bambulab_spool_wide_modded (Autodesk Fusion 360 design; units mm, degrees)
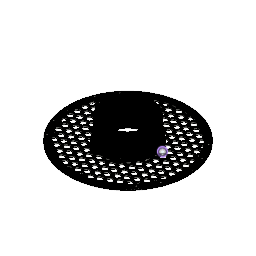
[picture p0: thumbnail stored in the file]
parameter "lattice_diameter" = 10.25
parameter "lattice_thickness" = 3.75
base_mesh_feature "Base Mesh Feature"
convert_mesh "Convert Mesh" bodies "bambulab_spool_wide"
sketch "Sketch13" plane through (0, 0, -16.75) normal (0, 0, 1) x axis (-1, 0, 0)
  line L1 (92.6217, -5.7502) -> (99.4206, -5.9753)
  line L2 (92.483, -7.6633) -> (92.6217, -5.7502)
  line L3 (99.4206, -5.9753) -> (92.483, -7.6633)
  circle C1 centre (15.0006, -94.8189) radius 1.75
  circle C2 centre (-15.0006, -94.8162) radius 1.75
  circle C3 centre (89.6159, -34.4185) radius 1.75
  circle C4 centre (74.6153, 60.4003) radius 1.75
  circle C5 centre (-15.0006, 94.8189) radius 1.75
  circle C6 centre (-89.6159, 34.4185) radius 1.75
  circle C7 centre (-74.6153, -60.4003) radius 1.75
  circle C8 centre (74.6129, -60.399) radius 1.75
  circle C9 centre (89.6135, 34.4171) radius 1.75
  circle C10 centre (15.0006, 94.8162) radius 1.75
  circle C11 centre (-74.6129, 60.399) radius 1.75
  circle C12 centre (-89.6135, -34.4171) radius 1.75
  point P1 (0, 0)
  point P7 (0, 0)
  coincident P1 P7
  dimension "d48" diameter C1 = 3.5
  dimension "d49" diameter C2 = 3.5
  dimension "d51" C-Pattern1-Angle = 360
  dimension "d53" C-Pattern2-Angle = 360
extrude "Extrude5" cut sketch "Sketch13" profile of C3 C4 C6 C7 C8 C9 C11 C12 against normal blind 25
sketch "Sketch14" plane through (0, 0, -17.85) normal (0, 0, 1) x axis (-1, 0, 0)
  line L1 (-23.297, 37.7968) -> (-24.4167, 37.0834)
  line L2 (-2.5625, 4.4384) -> (2.5625, 4.4384)
  line L3 (-5.125, 0) -> (-2.5625, 4.4384)
  line L4 (-2.5625, -4.4384) -> (-5.125, 0)
  line L5 (2.5625, -4.4384) -> (-2.5625, -4.4384)
  line L6 (5.125, 0) -> (2.5625, -4.4384)
  line L7 (2.5625, 4.4384) -> (5.125, 0)
  line L8 (5.125, -12.6268) -> (2.5625, -17.0651)
  line L9 (2.5625, -8.1884) -> (5.125, -12.6268)
  line L10 (-2.5625, -8.1884) -> (2.5625, -8.1884)
  line L11 (-5.125, -12.6268) -> (-2.5625, -8.1884)
  line L12 (-2.5625, -17.0651) -> (-5.125, -12.6268)
  line L13 (2.5625, -17.0651) -> (-2.5625, -17.0651)
  line L14 (0, -45.5) -> (0, 45.5)
  line L15 (-37, 0) -> (37, 0)
  line L16 (16.0601, -6.3134) -> (13.4976, -10.7518)
  line L17 (13.4976, -1.875) -> (16.0601, -6.3134)
  line L18 (8.3726, -1.875) -> (13.4976, -1.875)
  line L19 (5.8101, -6.3134) -> (8.3726, -1.875)
  line L20 (8.3726, -10.7518) -> (5.8101, -6.3134)
  line L21 (13.4976, -10.7518) -> (8.3726, -10.7518)
  line L22 (13.4976, 10.7518) -> (16.0601, 6.3134)
  line L23 (8.3726, 10.7518) -> (13.4976, 10.7518)
  line L24 (5.8101, 6.3134) -> (8.3726, 10.7518)
  line L25 (8.3726, 1.875) -> (5.8101, 6.3134)
  line L26 (13.4976, 1.875) -> (8.3726, 1.875)
  line L27 (16.0601, 6.3134) -> (13.4976, 1.875)
  line L28 (-5.125, -17.0651) -> (-5.125, 10.7518)
  line L29 (16.0601, -17.0651) -> (16.0601, 10.7518)
  line L30 (-5.125, 10.7518) -> (16.0601, 10.7518)
  line L31 (-5.125, -17.0651) -> (16.0601, -17.0651)
  line L32 (-92.4279, -85.5158) -> (-89.8654, -89.9542)
  line L33 (-89.8654, -89.9542) -> (-92.4279, -94.3926)
  line L34 (-92.4279, -94.3926) -> (-97.5529, -94.3926)
  line L35 (-97.5529, -94.3926) -> (-100.1154, -89.9542)
  line L36 (-100.1154, -89.9542) -> (-97.5529, -85.5158)
  line L37 (-97.5529, -85.5158) -> (-92.4279, -85.5158)
  line L38 (-92.4279, -98.1426) -> (-89.8654, -102.581)
  line L39 (-97.5529, -98.1426) -> (-92.4279, -98.1426)
  line L40 (-100.1154, -102.581) -> (-97.5529, -98.1426)
  line L41 (-97.5529, -107.0194) -> (-100.1154, -102.581)
  line L42 (-92.4279, -107.0194) -> (-97.5529, -107.0194)
  line L43 (-89.8654, -102.581) -> (-92.4279, -107.0194)
  line L44 (-100.8005, -96.2676) -> (-103.363, -100.706)
  line L45 (-103.363, -91.8292) -> (-100.8005, -96.2676)
  line L46 (-108.488, -91.8292) -> (-103.363, -91.8292)
  line L47 (-111.0505, -96.2676) -> (-108.488, -91.8292)
  line L48 (-108.488, -100.706) -> (-111.0505, -96.2676)
  line L49 (-103.363, -100.706) -> (-108.488, -100.706)
  line L50 (-108.488, -104.456) -> (-103.363, -104.456)
  line L51 (-103.363, -104.456) -> (-100.8005, -108.8944)
  line L52 (-100.8005, -108.8944) -> (-103.363, -113.3327)
  line L53 (-103.363, -113.3327) -> (-108.488, -113.3327)
  line L54 (-108.488, -113.3327) -> (-111.0505, -108.8944)
  line L55 (-111.0505, -108.8944) -> (-108.488, -104.456)
  line L56 (-71.2428, -85.5158) -> (-68.6803, -89.9542)
  line L57 (-68.6803, -89.9542) -> (-71.2428, -94.3926)
  line L58 (-71.2428, -94.3926) -> (-76.3678, -94.3926)
  line L59 (-76.3678, -94.3926) -> (-78.9303, -89.9542)
  line L60 (-78.9303, -89.9542) -> (-76.3678, -85.5158)
  line L61 (-76.3678, -85.5158) -> (-71.2428, -85.5158)
  line L62 (-71.2428, -98.1426) -> (-68.6803, -102.581)
  line L63 (-76.3678, -98.1426) -> (-71.2428, -98.1426)
  line L64 (-78.9303, -102.581) -> (-76.3678, -98.1426)
  line L65 (-76.3678, -107.0194) -> (-78.9303, -102.581)
  line L66 (-71.2428, -107.0194) -> (-76.3678, -107.0194)
  line L67 (-68.6803, -102.581) -> (-71.2428, -107.0194)
  line L68 (-79.6154, -96.2676) -> (-82.1779, -100.706)
  line L69 (-82.1779, -91.8292) -> (-79.6154, -96.2676)
  line L70 (-87.3029, -91.8292) -> (-82.1779, -91.8292)
  line L71 (-89.8654, -96.2676) -> (-87.3029, -91.8292)
  line L72 (-87.3029, -100.706) -> (-89.8654, -96.2676)
  line L73 (-82.1779, -100.706) -> (-87.3029, -100.706)
  line L74 (-87.3029, -104.456) -> (-82.1779, -104.456)
  line L75 (-82.1779, -104.456) -> (-79.6154, -108.8944)
  line L76 (-79.6154, -108.8944) -> (-82.1779, -113.3327)
  line L77 (-82.1779, -113.3327) -> (-87.3029, -113.3327)
  line L78 (-87.3029, -113.3327) -> (-89.8654, -108.8944)
  line L79 (-89.8654, -108.8944) -> (-87.3029, -104.456)
  line L80 (-50.0577, -85.5158) -> (-47.4952, -89.9542)
  line L81 (-47.4952, -89.9542) -> (-50.0577, -94.3926)
  line L82 (-50.0577, -94.3926) -> (-55.1827, -94.3926)
  line L83 (-55.1827, -94.3926) -> (-57.7452, -89.9542)
  line L84 (-57.7452, -89.9542) -> (-55.1827, -85.5158)
  line L85 (-55.1827, -85.5158) -> (-50.0577, -85.5158)
  line L86 (-50.0577, -98.1426) -> (-47.4952, -102.581)
  line L87 (-55.1827, -98.1426) -> (-50.0577, -98.1426)
  line L88 (-57.7452, -102.581) -> (-55.1827, -98.1426)
  line L89 (-55.1827, -107.0194) -> (-57.7452, -102.581)
  line L90 (-50.0577, -107.0194) -> (-55.1827, -107.0194)
  line L91 (-47.4952, -102.581) -> (-50.0577, -107.0194)
  line L92 (-58.4303, -96.2676) -> (-60.9928, -100.706)
  line L93 (-60.9928, -91.8292) -> (-58.4303, -96.2676)
  line L94 (-66.1178, -91.8292) -> (-60.9928, -91.8292)
  line L95 (-68.6803, -96.2676) -> (-66.1178, -91.8292)
  line L96 (-66.1178, -100.706) -> (-68.6803, -96.2676)
  line L97 (-60.9928, -100.706) -> (-66.1178, -100.706)
  line L98 (-66.1178, -104.456) -> (-60.9928, -104.456)
  line L99 (-60.9928, -104.456) -> (-58.4303, -108.8944)
  line L100 (-58.4303, -108.8944) -> (-60.9928, -113.3327)
  line L101 (-60.9928, -113.3327) -> (-66.1178, -113.3327)
  line L102 (-66.1178, -113.3327) -> (-68.6803, -108.8944)
  line L103 (-68.6803, -108.8944) -> (-66.1178, -104.456)
  line L104 (-28.8726, -85.5158) -> (-26.3101, -89.9542)
  line L105 (-26.3101, -89.9542) -> (-28.8726, -94.3926)
  line L106 (-28.8726, -94.3926) -> (-33.9976, -94.3926)
  line L107 (-33.9976, -94.3926) -> (-36.5601, -89.9542)
  line L108 (-36.5601, -89.9542) -> (-33.9976, -85.5158)
  line L109 (-33.9976, -85.5158) -> (-28.8726, -85.5158)
  line L110 (-28.8726, -98.1426) -> (-26.3101, -102.581)
  line L111 (-33.9976, -98.1426) -> (-28.8726, -98.1426)
  line L112 (-36.5601, -102.581) -> (-33.9976, -98.1426)
  line L113 (-33.9976, -107.0194) -> (-36.5601, -102.581)
  line L114 (-28.8726, -107.0194) -> (-33.9976, -107.0194)
  line L115 (-26.3101, -102.581) -> (-28.8726, -107.0194)
  line L116 (-37.2452, -96.2676) -> (-39.8077, -100.706)
  line L117 (-39.8077, -91.8292) -> (-37.2452, -96.2676)
  line L118 (-44.9327, -91.8292) -> (-39.8077, -91.8292)
  line L119 (-47.4952, -96.2676) -> (-44.9327, -91.8292)
  line L120 (-44.9327, -100.706) -> (-47.4952, -96.2676)
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  point P1 (0, 0)
  point P4 (0, 0)
  point P5 (0, 0)
  point P6 (0, 0)
  point P13 (0, 0)
  point P20 (0, -12.6268)
  point P9 (-5.125, 0)
  point P26 (16.0601, -6.3134)
  point P41 (16.0601, -17.0651)
  point P42 (-5.125, -17.0651)
  point P39 (-5.125, 10.7518)
  point P40 (16.0601, 10.7518)
  point P12 (5.125, 0)
  point P7 (2.5625, 4.4384)
  point P10 (-2.5625, -4.4384)
  point P15 (5.125, -12.6268)
  point P18 (-5.125, -12.6268)
  point P14 (2.5625, -17.0651)
  point P17 (-2.5625, -8.1884)
  point P29 (5.8101, -6.3134)
  point P32 (16.0601, 6.3134)
  point P35 (5.8101, 6.3134)
  coincident P1 P4
  coincident P1 P5
  coincident P1 P6
  coincident P5 P13
  vertical L14
  horizontal L15
  coincident P1 L14
  midpoint P4 L15
  midpoint P1 L14
  coincident P20 L14
  parallel L5 L15
  parallel L15 L21
  parallel L15 L26
  vertical L28
  vertical L29
  coincident P9 L28
  coincident P26 L29
  perpendicular L29 L30
  horizontal L31
  collinear L23 L30
  collinear L13 L31
  coincident L29 P41
  coincident L28 P42
  coincident P39 L30
  coincident L29 P40
  dimension "d56" diameter = 183.4
  dimension "d57" diameter = 89
  dimension "d62" diameter = 179.65 (= "183.4 mm - lattice_thickness")
  dimension "d63" distance P9 P12 = 10.25 (= "lattice_diameter")
  dimension "d64" distance P7 P10 = 10.25 (= "lattice_diameter")
  dimension "d65" distance P15 P18 = 10.25 (= "lattice_diameter")
  dimension "d66" distance P14 P17 = 10.25 (= "lattice_diameter")
  dimension "d67" distance L5 L10 = 3.75 (= "lattice_thickness")
  dimension "d68" distance P26 P29 = 10.25 (= "lattice_diameter")
  dimension "d69" distance L6 L19 = 3.75 (= "lattice_thickness")
  dimension "d70" distance L9 L20 = 3.75 (= "lattice_thickness")
  dimension "d71" distance P32 P35 = 10.25 (= "lattice_diameter")
  dimension "d72" distance L18 L26 = 3.75 (= "lattice_thickness")
  dimension "d73" distance L7 L25 = 3.75 (= "lattice_thickness")
  dimension "d74" distance P41 P42 = 21.1851
  dimension "d75" distance P40 P41 = 27.8169
  dimension "d78" R-Pattern1-uDistance = 21.1851
  dimension "d79" R-Pattern1-vDistance = 24.0669 (= "27.816899 mm - lattice_thickness")
extrude "Extrude6" cut sketch "Sketch14" distance 30
work_plane "WorkPlane3" RotateAngle 45
sketch "Sketch16" plane through (27.1973, 30.4798, 1.2) normal (0.7071, 0.7071, -0.0003) x axis (-0.0041, 0.0036, -1)
  line L1 (17.7883, -26.5886) -> (17.7779, -28.5173)
  circle C1 centre (17.5808, -27.9755) radius 1.1
  point P2 (17.5808, -27.9755)
  dimension "d84" diameter C1 = 2.2
  dimension "d85" distance P2 L1 = 0.2
extrude "Extrude7" cut sketch "Sketch16" profile of C1 against normal blind 13
work_plane "WorkPlane4" RotateAngle 120
sketch "Sketch17" plane through (37.7529, -15.5941, 1.2) normal (0.6096, -0.7926, -0.0143) x axis (0.0109, 0.0265, -0.9996)
  line L1 (19.3005, 6.8332) -> (19.2658, 5.9127)
  circle C1 centre (17.9921, 7.9641) radius 1.1
  point P2 (17.9921, 7.9641)
  dimension "d89" diameter C1 = 2.2
  dimension "d93" distance P2 L1 = 1.35
extrude "Extrude8" cut sketch "Sketch17" profile of C1 against normal blind 10.5
named bodies: "bambulab_spool_wide"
